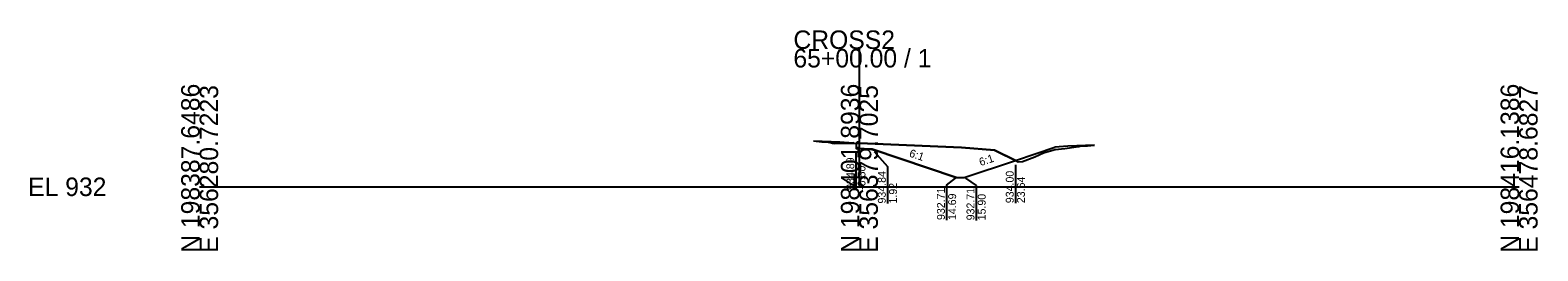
# Model space of a CAD drawing. Extents: x -26 to 203, y -10 to 14021.
# Drawn here: x -25.7 to 202.8, y 5990.3 to 6023.7 of the extents above; entities that cross this region are included whole.
import ezdxf

# ---------------------------------------------------------------- set-up
doc = ezdxf.new("R2010")
doc.units = 0
for name, color, linetype in [('Default', 7, 'Continuous'), ('P_E_XS_Ground', 7, 'Continuous'), ('P_XS', 7, 'Continuous'), ('P_XS_EAR_CommonGrnd', 7, 'Continuous'), ('P_XS_Lane', 7, 'Continuous'), ('P_XS_Rock', 7, 'Continuous')]:
    doc.layers.add(name, color=color, linetype=linetype)

msp = doc.modelspace()

# ---------------------------------------------------------------- linework, layer by layer
at = {"layer": 'Default'}
for p, q in [((100, 6000), (100, 6020.87)), ((0, 6000), (100, 6000)), ((100, 6000), (200, 6000))]:
    msp.add_line(p, q, dxfattribs=at)
at = {"layer": 'P_E_XS_Ground'}
for p, q in [((93.04, 6006.96), (94.32, 6006.81)), ((94.32, 6006.81), (95.26, 6006.75)), ((95.26, 6006.75), (95.57, 6006.71)), ((95.57, 6006.71), (95.91, 6006.63)), ((95.91, 6006.63), (96.3, 6006.56)), ((96.3, 6006.56), (99.5, 6006.61)), ((99.5, 6006.61), (100, 6006.59)), ((100, 6006.59), (115.5, 6005.97)), ((115.5, 6005.97), (120.5, 6005.57)), ((131.13, 6005.8), (132.84, 6006.03)), ((132.84, 6006.03), (133.24, 6006.11)), ((133.24, 6006.11), (133.55, 6006.19)), ((133.55, 6006.19), (134.57, 6006.19)), ((134.57, 6006.19), (135.62, 6006.31)), ((120.5, 6005.57), (124.06, 6003.79)), ((124.06, 6003.79), (124.73, 6003.84)), ((124.73, 6003.84), (126.59, 6004.52)), ((126.59, 6004.52), (127.91, 6005.13)), ((127.91, 6005.13), (128.96, 6005.43)), ((128.96, 6005.43), (129.68, 6005.63)), ((129.68, 6005.63), (131.13, 6005.8))]:
    msp.add_line(p, q, dxfattribs=at)
at = {"layer": 'P_XS'}
for p, q in [((93.04, 6006.96), (97.04, 6006.8)), ((97.04, 6006.8), (99.04, 6006.64)), ((99.14, 6006.6), (99.04, 6006.64)), ((123.64, 6004), (129.62, 6005.99)), ((131.62, 6006.15), (129.62, 6005.99)), ((135.62, 6006.31), (131.62, 6006.15))]:
    msp.add_line(p, q, dxfattribs=at)
at = {"layer": 'P_XS_EAR_CommonGrnd'}
msp.add_lwpolyline([(114.69, 6001.42), (115.9, 6001.42), (123.64, 6004), (120.5, 6005.57), (115.5, 6005.97), (100, 6006.59), (99.5, 6006.61), (99.5, 6005.78), (101.92, 6005.68)], close=True, dxfattribs=at)
at = {"layer": 'P_XS_Lane'}
for p, q in [((99.5, 6006.61), (99.5, 6005.78)), ((101.92, 6005.68), (99.5, 6005.78)), ((114.69, 6001.42), (101.92, 6005.68)), ((115.9, 6001.42), (123.64, 6004)), ((114.69, 6001.42), (115.9, 6001.42))]:
    msp.add_line(p, q, dxfattribs=at)
at = {"layer": 'P_XS_Rock'}
for p, q in [((99.47, 6005.13), (99.47, 5999.54)), ((102.23, 6005.33), (104.25, 6003.06)), ((104.25, 6003.06), (104.25, 5997.47)), ((113.21, 6000.26), (114.55, 6001.3)), ((116.09, 6001.29), (117.69, 6000.21)), ((123.64, 6003.31), (123.64, 5997.52)), ((113.21, 6000.26), (113.21, 5994.97)), ((117.69, 6000.21), (117.69, 5994.92))]:
    msp.add_line(p, q, dxfattribs=at)

# ---------------------------------------------------------------- texts
at = {"layer": 'Default'}
for s, p in [('CROSS2', (90, 6020.87)), ('65+00.00 / 1', (90, 6018.07)), ('EL 932', (-26, 5998.6))]:
    msp.add_text(s, height=2.8, dxfattribs=at).set_placement(p)
for s, p in [('N 198387.6486', (0, 5990)), ('E 356280.7223', (2.8, 5990)), ('N 198401.8936', (100, 5990)), ('E 356379.7025', (102.8, 5990)), ('N 198416.1386', (200, 5990)), ('E 356478.6827', (202.8, 5990))]:
    msp.add_text(s, height=2.8, rotation=90, dxfattribs=at).set_placement(p)
at = {"layer": 'P_XS_Rock'}
for s, rotation, p in [('934.89', 90, (99.22, 5999.54)), ('6:1', 341.5651, (107.46, 6004.6)), ('6:1', 18.4349, (118.38, 6003.13)), ('-0.50', 90, (100.92, 5999.54)), ('934.84', 90, (104, 5997.47)), ('934.00', 90, (123.39, 5997.52)), ('23.64', 90, (125.09, 5997.52)), ('1.92', 90, (105.7, 5997.47)), ('932.71', 90, (112.96, 5994.97)), ('932.71', 90, (117.44, 5994.92)), ('14.69', 90, (114.66, 5994.97)), ('15.90', 90, (119.14, 5994.92))]:
    msp.add_text(s, height=1.2, rotation=rotation, dxfattribs=at).set_placement(p)

doc.saveas('drawing.dxf')
